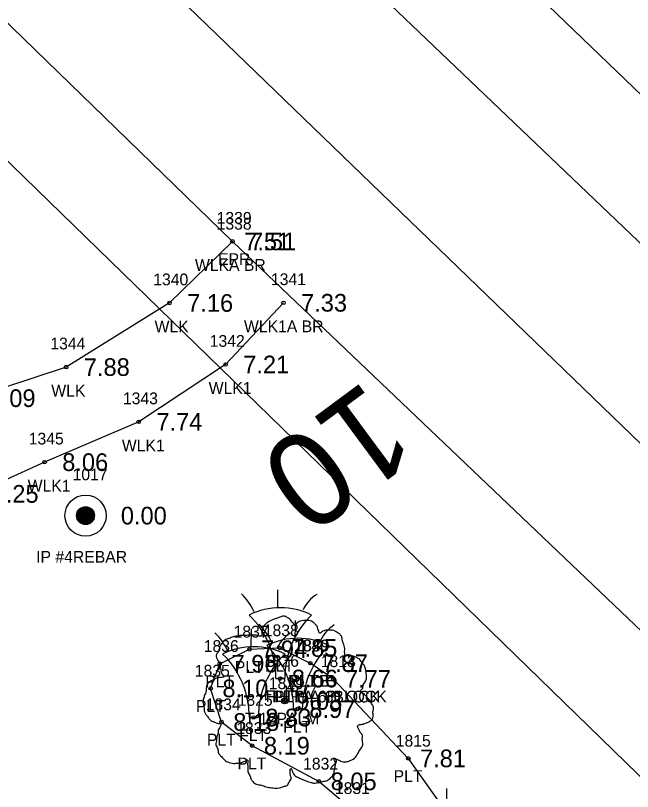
# Model space of a CAD drawing. Extents: x 2608598 to 2610682, y 641451 to 643526.
# Drawn here: x 2609105.8 to 2609158.2, y 643012.1 to 643078.1 of the extents above; entities that cross this region are included whole.
import ezdxf

# ---------------------------------------------------------------- set-up
doc = ezdxf.new("R2010")
doc.units = 0
for name, color, linetype in [('RD_EX_BldgApp', 7, 'Continuous'), ('RD_EX_BldgApp_txCode', 7, 'Continuous'), ('RD_EX_DR_Pipe', 7, 'Continuous'), ('RD_EX_DV_Prop_txCode', 7, 'Continuous'), ('RD_EX_DV_PropPin', 7, 'Continuous'), ('RD_EX_Misc', 7, 'Continuous'), ('RD_EX_Misc_txCode', 7, 'Continuous'), ('RD_EX_Road', 7, 'Continuous'), ('RD_EX_Road_txCode', 7, 'Continuous'), ('RD_EX_TX_BldgApp_ELEV', 7, 'Continuous'), ('RD_EX_TX_DV_Prop_ELEV', 7, 'Continuous'), ('RD_EX_TX_Misc_ELEV', 7, 'Continuous'), ('RD_EX_TX_Road_ELEV', 7, 'Continuous'), ('RD_EX_TX_VEG_ELEV', 7, 'Continuous'), ('RD_EX_VEG', 7, 'Continuous'), ('RD_EX_VEG_txCode', 7, 'Continuous'), ('RD_HC_Cl', 7, 'Continuous'), ('RD_HC_TX_Sta50', 7, 'Continuous'), ('RD_SMD_Locator', 7, 'Continuous')]:
    doc.layers.add(name, color=color, linetype=linetype)

msp = doc.modelspace()

# ---------------------------------------------------------------- linework, layer by layer
at = {"layer": 'RD_EX_BldgApp'}
for p, q in [((2609132.758, 643021.706), (2609130.805, 643023.041)), ((2609127.891, 643021.753), (2609128.641, 643021.753)), ((2609129.377, 643019.162), (2609130.127, 643019.162)), ((2609125.634, 643018.442), (2609126.384, 643018.442))]:
    msp.add_line(p, q, dxfattribs=at)
msp.add_lwpolyline([(2609132.758, 643021.706), (2609139.134, 643014.954), (2609145.621, 643005.793), (2609147.215, 643001.878), (2609146.641, 642999.98), (2609142.958, 642998.02), (2609139.97, 642998.663), (2609137.44, 643002.351), (2609135.286, 643009.164), (2609133.96, 643010.931), (2609131.543, 643013.004), (2609125.865, 643016.031), (2609123.266, 643018.046), (2609122.34, 643020.902), (2609123.122, 643022.999), (2609125.636, 643024.221), (2609128.202, 643024.335), (2609130.805, 643023.041)], dxfattribs=at)
for centre, radius, start, end in [((2609090.184, 643029.091), 37.876, 358.06712, 0.27154), ((2609121.573, 643025.396), 4.895, 24.32791, 46.26654), ((2609133.154, 643026.146), 3.283, 123.29064, 154.48862), ((2609128.266, 643021.753), 5.997, 63.77943, 116.22057), ((2609120.391, 643021.753), 7.5, 0, 45.83662), ((2609136.141, 643021.753), 7.5, 134.16338, 180), ((2609123.059, 643022.805), 4.895, 24.32791, 46.26654), ((2609091.67, 643026.5), 37.876, 358.06712, 0.27154), ((2609087.928, 643025.78), 37.876, 358.06712, 0.27154), ((2609134.64, 643023.555), 3.283, 123.29064, 154.48862), ((2609119.317, 643022.084), 4.895, 24.32791, 46.26654), ((2609129.752, 643019.162), 5.997, 63.77943, 116.22057), ((2609130.898, 643022.835), 3.283, 123.29064, 154.48862), ((2609126.009, 643018.442), 5.997, 63.77943, 116.22057), ((2609121.877, 643019.162), 7.5, 0, 45.83662), ((2609137.627, 643019.162), 7.5, 134.16338, 180), ((2609118.134, 643018.442), 7.5, 0, 45.83662), ((2609133.884, 643018.442), 7.5, 134.16338, 180), ((2609104.532, 643012.216), 37.876, 358.06712, 0.27154)]:
    msp.add_arc(centre, radius, start, end, dxfattribs=at)
at = {"layer": 'RD_EX_DR_Pipe'}
msp.add_line((2609069.044, 643157.849), (2609202.653, 643029.203), dxfattribs=at)
msp.add_lwpolyline([(2609067.894, 643101.844), (2609174.278, 642998.399), (2609174.637, 642998.15), (2609264.347, 642914.358)], dxfattribs=at)
at = {"layer": 'RD_EX_DV_PropPin'}
for p, q in [((2609111.287, 643034.941), (2609111.287, 643036.21)), ((2609111.322, 643034.919), (2609111.322, 643036.232)), ((2609111.357, 643034.9), (2609111.357, 643036.251)), ((2609111.392, 643034.883), (2609111.392, 643036.268)), ((2609111.427, 643034.868), (2609111.427, 643036.283)), ((2609111.462, 643034.855), (2609111.462, 643036.296)), ((2609111.497, 643034.844), (2609111.497, 643036.307)), ((2609111.532, 643034.835), (2609111.532, 643036.316)), ((2609111.567, 643034.827), (2609111.567, 643036.323)), ((2609111.602, 643034.822), (2609111.602, 643036.329)), ((2609111.637, 643034.818), (2609111.637, 643036.333)), ((2609111.672, 643034.815), (2609111.672, 643036.336)), ((2609111.707, 643034.814), (2609111.707, 643036.336)), ((2609111.742, 643034.815), (2609111.742, 643036.336)), ((2609111.777, 643034.818), (2609111.777, 643036.333)), ((2609111.812, 643034.822), (2609111.812, 643036.329)), ((2609111.847, 643034.827), (2609111.847, 643036.323)), ((2609111.882, 643034.835), (2609111.882, 643036.316)), ((2609111.917, 643034.844), (2609111.917, 643036.307)), ((2609111.952, 643034.855), (2609111.952, 643036.296)), ((2609111.987, 643034.868), (2609111.987, 643036.283)), ((2609112.023, 643034.883), (2609112.023, 643036.268)), ((2609112.058, 643034.9), (2609112.058, 643036.251)), ((2609112.093, 643034.919), (2609112.093, 643036.232)), ((2609112.128, 643034.941), (2609112.128, 643036.21)), ((2609110.972, 643035.379), (2609110.972, 643035.771)), ((2609111.007, 643035.277), (2609111.007, 643035.873)), ((2609111.042, 643035.206), (2609111.042, 643035.945)), ((2609111.077, 643035.149), (2609111.077, 643036.002)), ((2609111.112, 643035.101), (2609111.112, 643036.049)), ((2609111.147, 643035.06), (2609111.147, 643036.09)), ((2609111.182, 643035.025), (2609111.182, 643036.126)), ((2609111.217, 643034.993), (2609111.217, 643036.157)), ((2609111.252, 643034.965), (2609111.252, 643036.185)), ((2609112.163, 643034.965), (2609112.163, 643036.185)), ((2609112.198, 643034.993), (2609112.198, 643036.157)), ((2609112.233, 643035.025), (2609112.233, 643036.126)), ((2609112.268, 643035.06), (2609112.268, 643036.09)), ((2609112.303, 643035.101), (2609112.303, 643036.049)), ((2609112.338, 643035.149), (2609112.338, 643036.002)), ((2609112.373, 643035.206), (2609112.373, 643035.945)), ((2609112.408, 643035.277), (2609112.408, 643035.873)), ((2609112.443, 643035.379), (2609112.443, 643035.771))]:
    msp.add_line(p, q, dxfattribs=at)
for radius in [1.75, 0.761]:
    msp.add_circle((2609111.707, 643035.575), radius, dxfattribs=at)
at = {"layer": 'RD_EX_Misc'}
for points in [[(2609124.194, 643058.866), (2609118.846, 643053.637), (2609110.064, 643048.192), (2609102.056, 643045.551), (2609097.25, 643042.284), (2609093.164, 643036.153), (2609090.416, 643033.2), (2609082.12, 643031.658), (2609076.379, 643032.084)], [(2609128.527, 643053.654), (2609123.609, 643048.413), (2609116.229, 643043.537), (2609108.226, 643040.117), (2609102.312, 643037.423), (2609097.205, 643029.996), (2609091.903, 643026.267), (2609088.7, 643025.198), (2609088.313, 643022.329), (2609089.846, 643020.574), (2609084.277, 643015.781), (2609081.235, 643019.267)]]:
    msp.add_lwpolyline(points, dxfattribs=at)
at = {"layer": 'RD_EX_Road'}
for points in [[(2608806.889, 643364.989), (2608810.184, 643361.1), (2608820.754, 643351.249), (2608881.81, 643292.235), (2608917.833, 643257.495), (2608933.208, 643242.709), (2608954.068, 643222.833), (2609026.064, 643154.189), (2609039.601, 643139.963), (2609073.879, 643106.954), (2609100.48, 643081.888), (2609124.194, 643058.866), (2609171.612, 643013.711), (2609183.195, 643002.284), (2609197.913, 642988.365), (2609247.586, 642940.954), (2609328.02, 642863.599), (2609402.609, 642790.299), (2609474.235, 642720.69), (2609483.838, 642711.579), (2609495.782, 642699.917), (2609509.808, 642686.45)], [(2609042.495, 643170.94), (2609058.512, 643155.458), (2609096.06, 643119.372), (2609116.51, 643099.11), (2609162.396, 643055.351), (2609177.209, 643041.342), (2609188.353, 643030.959), (2609199.912, 643019.764), (2609205.803, 643014.044), (2609217.132, 643003.172), (2609235.835, 642983.899), (2609237.032, 642983.51), (2609256.803, 642965.042), (2609258.491, 642962.514), (2609263.653, 642957.664), (2609344.713, 642879.888)]]:
    msp.add_lwpolyline(points, dxfattribs=at)
at = {"layer": 'RD_EX_VEG'}
for centre, radius in [((2609128.628, 643019.835), 0.25), ((2609128.615, 643019.816), 0.0001)]:
    msp.add_circle(centre, radius, dxfattribs=at)
for points in [[(2609128.76, 643027.002), (2609128.46, 643027.027), (2609128.135, 643026.927), (2609127.885, 643026.828), (2609127.66, 643026.753), (2609127.436, 643026.653), (2609127.136, 643026.478), (2609126.911, 643026.278), (2609126.786, 643026.028), (2609126.736, 643025.803), (2609126.686, 643025.528), (2609126.686, 643025.353), (2609126.561, 643025.328), (2609126.411, 643025.353), (2609126.161, 643025.428), (2609125.911, 643025.428), (2609125.661, 643025.428), (2609125.311, 643025.403), (2609124.962, 643025.403), (2609124.687, 643025.353), (2609124.362, 643025.303), (2609123.987, 643025.178), (2609123.637, 643025.053), (2609123.337, 643024.803), (2609123.087, 643024.329), (2609122.962, 643023.979), (2609122.813, 643023.729), (2609122.962, 643023.279), (2609123.137, 643022.929), (2609123.162, 643022.729), (2609123.237, 643022.305), (2609123.337, 643022.08), (2609123.462, 643021.88), (2609123.387, 643021.855), (2609123.012, 643021.805), (2609122.713, 643021.705), (2609122.288, 643021.48), (2609122.063, 643021.255), (2609121.963, 643020.93), (2609121.938, 643020.58), (2609121.838, 643020.38), (2609121.763, 643020.105), (2609121.738, 643020.03), (2609121.688, 643019.706), (2609121.788, 643019.256), (2609121.813, 643018.906), (2609121.938, 643018.681), (2609122.088, 643018.506), (2609122.263, 643018.256), (2609122.663, 643018.031), (2609122.987, 643017.931), (2609123.187, 643017.906), (2609123.012, 643017.407), (2609122.962, 643017.057), (2609122.838, 643016.657), (2609122.838, 643016.582), (2609122.788, 643016.107), (2609122.937, 643015.782), (2609123.012, 643015.408), (2609123.187, 643015.183), (2609123.462, 643014.883), (2609123.787, 643014.658), (2609124.287, 643014.533), (2609124.687, 643014.558), (2609125.262, 643014.733), (2609125.511, 643014.808), (2609125.486, 643014.633), (2609125.511, 643014.258), (2609125.511, 643013.833), (2609125.661, 643013.508), (2609125.761, 643013.233), (2609125.911, 643012.984), (2609126.236, 643012.759), (2609126.636, 643012.684), (2609127.061, 643012.534), (2609127.511, 643012.459), (2609128.01, 643012.434), (2609128.61, 643012.584), (2609128.885, 643012.709), (2609128.985, 643012.884), (2609129.185, 643013.258), (2609129.135, 643013.483), (2609129.16, 643014.083), (2609129.26, 643013.908), (2609129.435, 643013.558), (2609129.934, 643013.258), (2609130.334, 643013.084), (2609130.809, 643012.934), (2609131.109, 643012.859), (2609131.584, 643012.934), (2609131.959, 643013.009), (2609132.333, 643013.134), (2609132.633, 643013.408), (2609132.808, 643013.683), (2609132.858, 643013.958), (2609132.933, 643014.333), (2609132.983, 643014.508)], [(2609132.983, 643014.508), (2609132.908, 643014.683), (2609132.858, 643014.933), (2609132.933, 643014.908), (2609133.108, 643014.858), (2609133.383, 643014.733), (2609133.608, 643014.658), (2609133.933, 643014.683), (2609134.208, 643014.783), (2609134.657, 643015.058), (2609134.932, 643015.532), (2609135.207, 643015.932), (2609135.282, 643016.257), (2609135.232, 643016.482), (2609135.207, 643016.982), (2609135.007, 643017.232), (2609134.957, 643017.357), (2609134.857, 643017.756), (2609134.932, 643017.806), (2609135.207, 643017.856), (2609135.582, 643017.981), (2609135.857, 643018.106), (2609136.082, 643018.281), (2609136.157, 643018.506), (2609136.132, 643018.906), (2609136.182, 643019.306), (2609136.107, 643019.456), (2609136.007, 643019.606), (2609135.932, 643019.806), (2609135.782, 643019.955), (2609135.682, 643020.105), (2609135.582, 643020.205), (2609135.457, 643020.355), (2609135.282, 643020.48), (2609135.132, 643020.53), (2609135.082, 643020.68), (2609135.232, 643020.88), (2609135.282, 643020.98), (2609135.307, 643021.205), (2609135.532, 643021.555), (2609135.582, 643021.955), (2609135.532, 643022.379), (2609135.482, 643022.654), (2609135.332, 643022.929), (2609135.132, 643023.179), (2609135.007, 643023.354), (2609134.832, 643023.479), (2609134.507, 643023.604), (2609134.258, 643023.654), (2609133.908, 643023.654), (2609133.708, 643023.704), (2609133.733, 643023.754), (2609133.733, 643023.904), (2609133.733, 643024.179), (2609133.658, 643024.628), (2609133.508, 643025.128), (2609133.508, 643025.153), (2609133.408, 643025.403), (2609133.183, 643025.603), (2609133.008, 643025.703), (2609132.808, 643025.828), (2609132.558, 643025.853), (2609132.258, 643025.853), (2609131.984, 643025.803), (2609131.784, 643025.703), (2609131.609, 643025.578), (2609131.534, 643025.728), (2609131.434, 643026.028), (2609131.384, 643026.178), (2609131.234, 643026.353), (2609131.009, 643026.553), (2609130.559, 643026.678), (2609129.934, 643026.603), (2609129.635, 643026.403), (2609129.485, 643026.228), (2609129.435, 643026.353), (2609129.235, 643026.553), (2609129.135, 643026.728), (2609128.96, 643026.853), (2609128.81, 643026.952), (2609128.71, 643027.002)]]:
    msp.add_spline(points, degree=3, dxfattribs=at)
at = {"layer": 'RD_HC_Cl'}
msp.add_line((2608814.812, 643373.733), (2610092.394, 642140.787), dxfattribs=at)
at = {"layer": 'RD_SMD_Locator'}
for centre in [(2609124.194, 643058.866), (2609124.194, 643058.866), (2609118.846, 643053.637), (2609128.527, 643053.654), (2609110.064, 643048.192), (2609123.609, 643048.413), (2609116.229, 643043.537), (2609108.226, 643040.117), (2609111.707, 643035.575), (2609125.636, 643024.221), (2609128.202, 643024.335), (2609123.122, 643022.999), (2609130.805, 643023.041), (2609130.805, 643023.041), (2609128.238, 643021.735), (2609132.758, 643021.706), (2609132.758, 643021.706), (2609122.34, 643020.902), (2609128.628, 643019.835), (2609129.724, 643019.144), (2609125.982, 643018.424), (2609123.266, 643018.046), (2609125.865, 643016.031), (2609139.134, 643014.954), (2609131.543, 643013.004)]:
    msp.add_circle(centre, 0.15, dxfattribs=at)

# ---------------------------------------------------------------- texts
at = {"layer": 'RD_EX_BldgApp_txCode'}
for s, p in [('1838', (2609126.855, 643025.335)), ('1837', (2609124.289, 643025.221)), ('1836', (2609121.752, 643023.999)), ('1840', (2609129.419, 643024.041)), ('1839', (2609129.459, 643024.041)), ('1826', (2609126.868, 643022.735)), ('1813', (2609131.695, 643022.706)), ('1814', (2609131.695, 643022.706)), ('PLT', (2609124.391, 643022.221)), ('PLT', (2609126.958, 643022.335)), ('1835', (2609120.993, 643021.902)), ('PLT', (2609121.878, 643020.999)), ('PLT1B', (2609128.923, 643021.041)), ('PLTB', (2609129.089, 643021.041)), ('1827', (2609128.378, 643020.144)), ('1825', (2609124.635, 643019.424)), ('FLT', (2609127.017, 643019.735)), ('PLT1A 6BLOCK', (2609127.569, 643019.706)), ('PLTA 6BLOCK', (2609127.735, 643019.706)), ('PLT', (2609121.096, 643018.902)), ('1834', (2609121.92, 643019.046)), ('1833', (2609124.518, 643017.031)), ('FLT', (2609128.504, 643017.144)), ('FLT', (2609124.761, 643016.424)), ('PLT', (2609122.022, 643016.046)), ('1815', (2609138.071, 643015.954)), ('PLT', (2609124.62, 643014.031)), ('1832', (2609130.197, 643014.004)), ('PLT', (2609137.89, 643012.954)), ('1831', (2609132.897, 643011.931))]:
    msp.add_text(s, height=1, dxfattribs=at).set_placement(p)
at = {"layer": 'RD_EX_DV_Prop_txCode'}
for s, p in [('1017', (2609110.605, 643038.575)), ('IP #4REBAR', (2609107.511, 643031.575))]:
    msp.add_text(s, height=1, dxfattribs=at).set_placement(p)
at = {"layer": 'RD_EX_Misc_txCode'}
for s, p in [('1339', (2609122.848, 643060.366)), ('WLKA BR', (2609121.005, 643056.366)), ('1340', (2609117.46, 643055.137)), ('1341', (2609127.464, 643055.154)), ('WLK', (2609117.578, 643051.137)), ('WLK1A BR', (2609125.172, 643051.154)), ('1344', (2609108.717, 643049.692)), ('1342', (2609122.262, 643049.913)), ('WLK1', (2609122.176, 643045.913)), ('WLK', (2609108.796, 643045.692)), ('1343', (2609114.883, 643045.037)), ('1345', (2609106.88, 643041.617)), ('WLK1', (2609114.796, 643041.037)), ('WLK1', (2609106.793, 643037.617))]:
    msp.add_text(s, height=1, dxfattribs=at).set_placement(p)
at = {"layer": 'RD_EX_Road_txCode'}
for s, p in [('1338', (2609122.848, 643059.866)), ('EPR', (2609122.966, 643056.866))]:
    msp.add_text(s, height=1, dxfattribs=at).set_placement(p)
at = {"layer": 'RD_EX_TX_BldgApp_ELEV'}
for s, p in [('7.94', (2609126.636, 643023.471)), ('7.85', (2609129.202, 643023.585)), ('7.96', (2609124.122, 643022.249)), ('7.87', (2609131.805, 643022.291)), ('7.87', (2609131.805, 643022.291)), ('8.66', (2609129.238, 643020.985)), ('7.77', (2609133.758, 643020.956)), ('7.77', (2609133.758, 643020.956)), ('8.10', (2609123.34, 643020.152)), ('8.97', (2609130.724, 643018.394)), ('8.83', (2609126.982, 643017.674)), ('8.18', (2609124.266, 643017.296)), ('8.19', (2609126.865, 643015.281)), ('7.81', (2609140.134, 643014.204)), ('8.05', (2609132.543, 643012.254))]:
    msp.add_text(s, height=1.5, dxfattribs=at).set_placement(p)
at = {"layer": 'RD_EX_TX_DV_Prop_ELEV'}
msp.add_text('0.00', height=1.5, dxfattribs=at).set_placement((2609114.707, 643034.825))
at = {"layer": 'RD_EX_TX_Misc_ELEV'}
for s, p in [('7.51', (2609125.694, 643058.116)), ('7.16', (2609120.346, 643052.887)), ('7.33', (2609130.027, 643052.904)), ('7.88', (2609111.564, 643047.442)), ('7.21', (2609125.109, 643047.663)), ('8.09', (2609103.556, 643044.801)), ('7.74', (2609117.729, 643042.787)), ('8.06', (2609109.726, 643039.367)), ('8.25', (2609103.812, 643036.673))]:
    msp.add_text(s, height=1.5, dxfattribs=at).set_placement(p)
at = {"layer": 'RD_EX_TX_Road_ELEV'}
msp.add_text('7.51', height=1.5, dxfattribs=at).set_placement((2609125.194, 643058.116))
at = {"layer": 'RD_EX_TX_VEG_ELEV'}
msp.add_text('9.03', height=1.5, dxfattribs=at).set_placement((2609129.628, 643019.085))
at = {"layer": 'RD_EX_VEG_txCode'}
for s, p in [('1829', (2609127.282, 643020.835)), ('T 12PALM', (2609125.258, 643017.835))]:
    msp.add_text(s, height=1, dxfattribs=at).set_placement(p)
at = {"layer": 'RD_HC_TX_Sta50'}
msp.add_text('10', height=8, rotation=216.4609, dxfattribs=at).set_placement((2609135.564, 643047.208))

doc.saveas('drawing.dxf')
